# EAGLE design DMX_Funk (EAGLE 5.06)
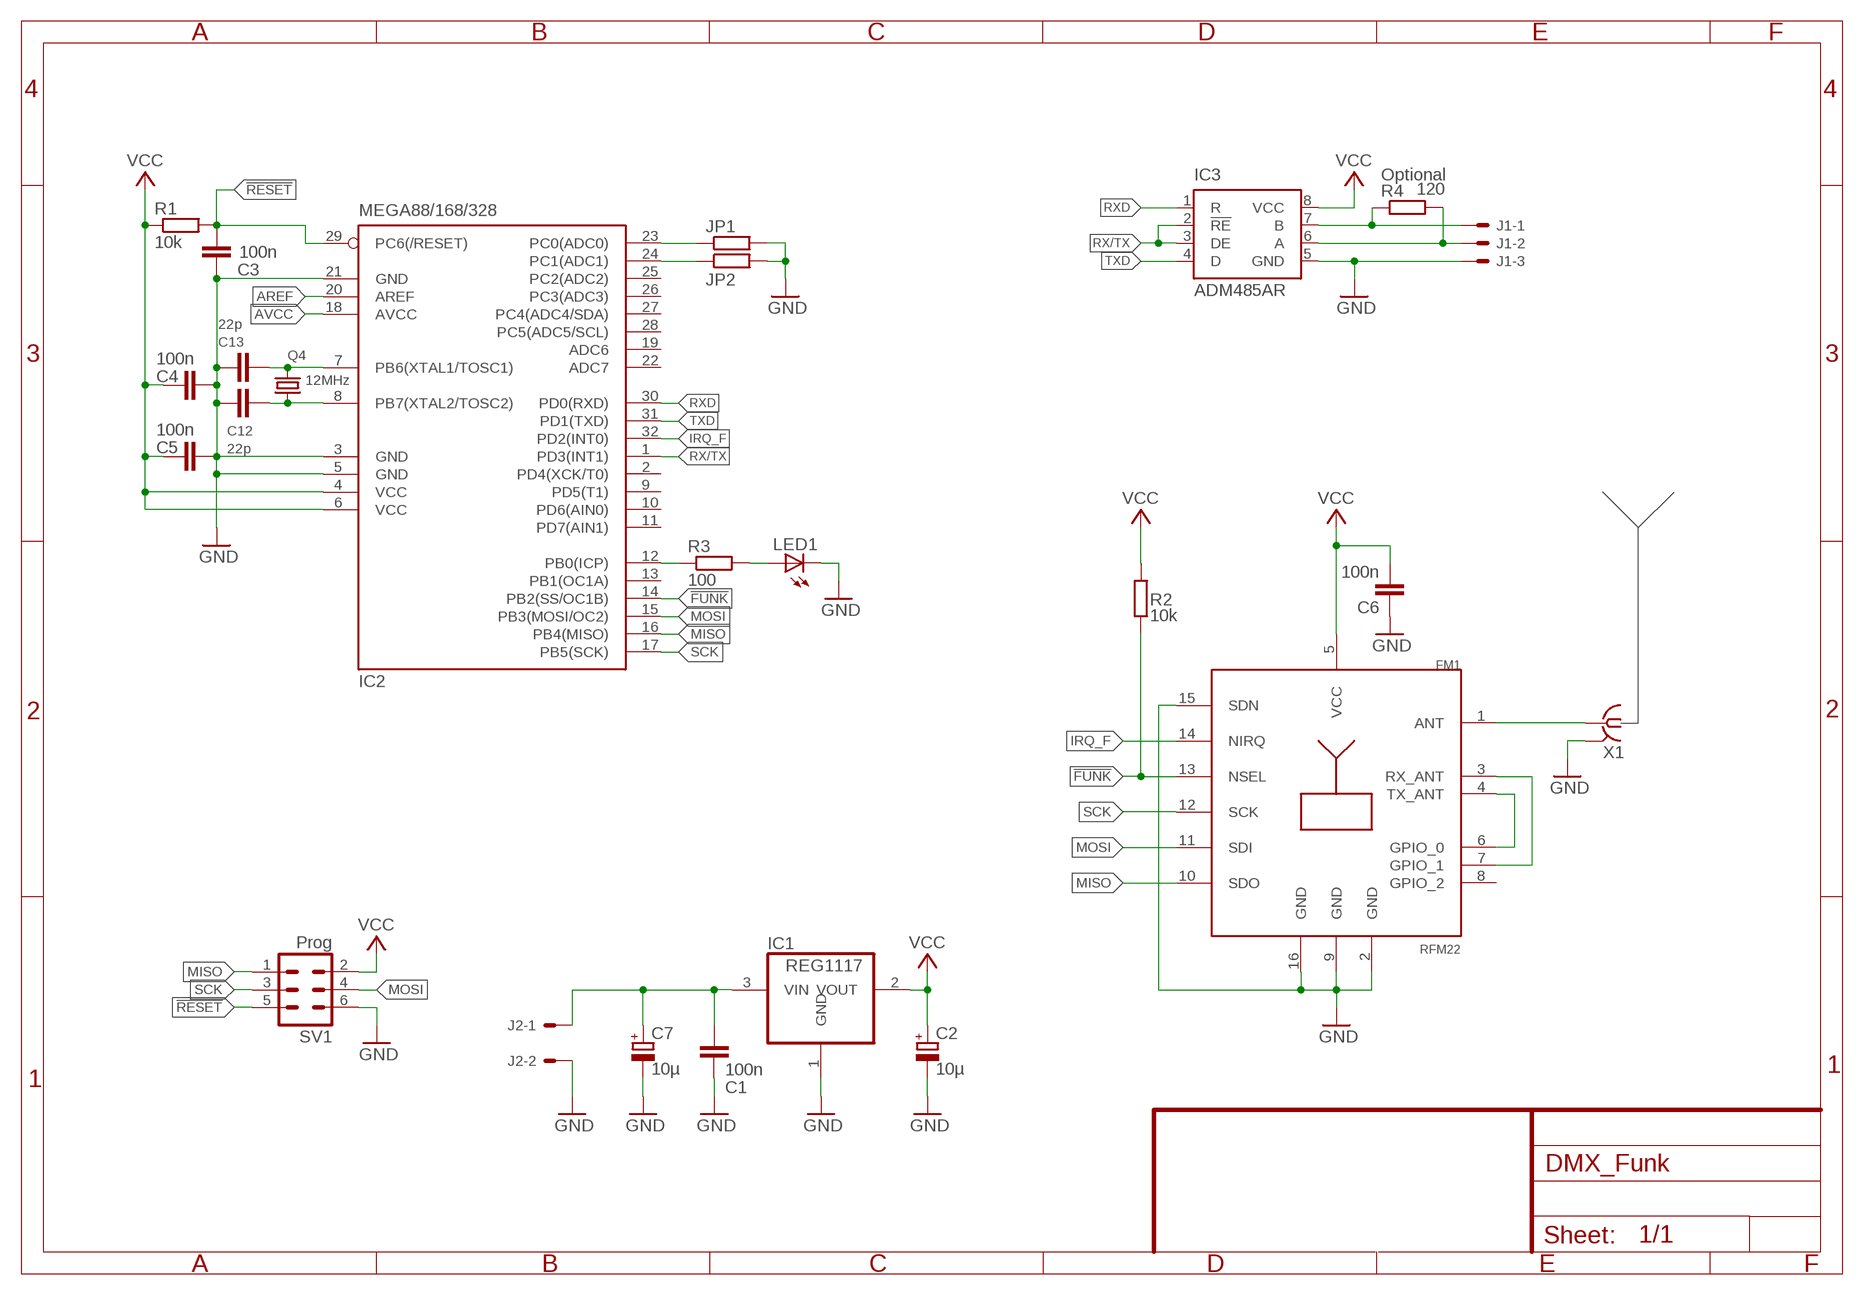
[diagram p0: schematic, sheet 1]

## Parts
C1  100n  C-EUC0805  [C0805]
C2  10µ  CPOL-EUSMCB  [SMC_B]
C3  100n  C-EUC0805  [C0805]
C4  100n  C-EUC0805  [C0805]
C5  100n  C-EUC0805  [C0805]
C6  100n  C-EUC0805  [C0805]
C7  10µ  CPOL-EUSMCB  [SMC_B]
C12  22p  C-EUC0805  [C0805]
C13  22p  C-EUC0805  [C0805]
FM1  RFM22  [RFM22]
IC1  REG1117  [SOT223]
IC2  MEGA88/168/328  MEGA8-AI  [TQFP32-08]
IC3  ADM485AR  SN65176D  [SO-08]
J1  22-27-2031-03  [6410-03]
J2  22-27-2021-02  [6410-02]
JP1  R-EU_R0402  [R0402]
JP2  R-EU_R0402  [R0402]
LED1  LEDSMT1206  [1206]
Q4  12MHz  CRYSTALCTS406  [CTS406]
R1  10k  R-EU_R0805  [R0805]
R2  10k  R-EU_R0805  [R0805]
R3  100  R-EU_R0805  [R0805]
R4  120  R-EU_M0805  [M0805]
SV1  Prog  ML6  [ML6]
X1  BU-SMC-V  [BU-SMC-V]

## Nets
!FUNK: FM1.13(NSEL) IC2.14(PB2(SS/OC1B)) R2.1
!RESET: C3.2 IC2.29(PC6(/RESET)) R1.2 SV1.5
AREF: IC2.20(AREF)
AVCC: IC2.18(AVCC)
GND: C1.1 C2.- C3.1 C4.2 C5.2 C6.1 C7.- C12.1 C13.1 FM1.2(GND) FM1.9(GND) FM1.15(SDN) FM1.16(GND) IC1.1(GND) IC2.3(GND) IC2.5(GND) IC2.21(GND) IC3.5(GND) J1.3 J2.2 JP1.2 JP2.2 LED1.C SV1.6 X1.2(GND)
IRQ_F: FM1.14(NIRQ) IC2.32(PD2(INT0))
MISO: FM1.10(SDO) IC2.16(PB4(MISO)) SV1.1
MOSI: FM1.11(SDI) IC2.15(PB3(MOSI/OC2)) SV1.4
N$1: FM1.4(TX_ANT) FM1.6(GPIO_0)
N$2: IC3.7(B) J1.1 R4.1
N$3: FM1.3(RX_ANT) FM1.7(GPIO_1)
N$4: FM1.1(ANT) X1.1
N$5: IC3.6(A) J1.2 R4.2
N$6: IC2.23(PC0(ADC0)) JP1.1
N$7: IC2.24(PC1(ADC1)) JP2.1
N$8: C1.2 C7.+ IC1.3(VIN) J2.1
N$18: IC2.12(PB0(ICP)) R3.1
N$19: LED1.A R3.2
N$26: C13.2 IC2.7(PB6(XTAL1/TOSC1)) Q4.3
N$27: C12.2 IC2.8(PB7(XTAL2/TOSC2)) Q4.1
RX/TX: IC2.1(PD3(INT1)) IC3.2(!RE) IC3.3(DE)
RXD: IC2.30(PD0(RXD)) IC3.1(R)
SCK: FM1.12(SCK) IC2.17(PB5(SCK)) SV1.3
TXD: IC2.31(PD1(TXD)) IC3.4(D)
VCC: C2.+ C4.1 C5.1 C6.2 FM1.5(VCC) IC1.2(VOUT) IC2.4(VCC) IC2.6(VCC) IC3.8(VCC) R1.1 R2.2 SV1.2
Unconnected: FM1.8(GPIO_2) IC2.2(PD4(XCK/T0)) IC2.9(PD5(T1)) IC2.10(PD6(AIN0)) IC2.11(PD7(AIN1)) IC2.13(PB1(OC1A)) IC2.19(ADC6) IC2.22(ADC7) IC2.25(PC2(ADC2)) IC2.26(PC3(ADC3)) IC2.27(PC4(ADC4/SDA)) IC2.28(PC5(ADC5/SCL))

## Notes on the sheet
- Optional

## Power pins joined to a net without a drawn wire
GND: X1.3(GND) X1.4(GND) X1.5(GND)

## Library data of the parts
C1 C3-C6 C12 C13 = rcl:C-EU: CAPACITOR, European symbol
C2 C7 = rcl:CPOL-EU: POLARIZED CAPACITOR, European symbol
FM1 = RFMxx:RFM22
IC1 = burr-brown:REG1117: 800mA and 1A Low Dropout (LDO) Positive Regulator 1.8V, 2.5V, 2.85V, 3.3V, 5V, and Adj
IC2 = atmel:MEGA8: MICROCONTROLLER 8 Kbytes FLASH, 1 kbytes SRAM, 512 bytes EEPROM, USART, 6-channel 10 bit ADC, 2-channel 8 bit ADC Pin compatible with Atmega48, ATMega88, ATMega168 Source: avr.lbr
IC3 = texas:SN65176: DIFFERENTIAL BUS TRANSCEIVER Source: http://focus.ti.com .. sn65176b.pdf
J1 = con-molex:22-?-03: CONNECTOR wire to board 2.54 mm (.1 inch) pitch header
J2 = con-molex:22-?-02: CONNECTOR
JP1 JP2 R1-R4 = rcl:R-EU_: RESISTOR, European symbol
LED1 = led:LED: LED
Q4 = crystal:CRYSTAL: CRYSTAL
SV1 = con-harting-ml:ML6: HARTING
X1 = con-coax:BU-SMC-V: FEMALE SMC CONNECTOR Radiall R112 426 distributor RS 295-5429

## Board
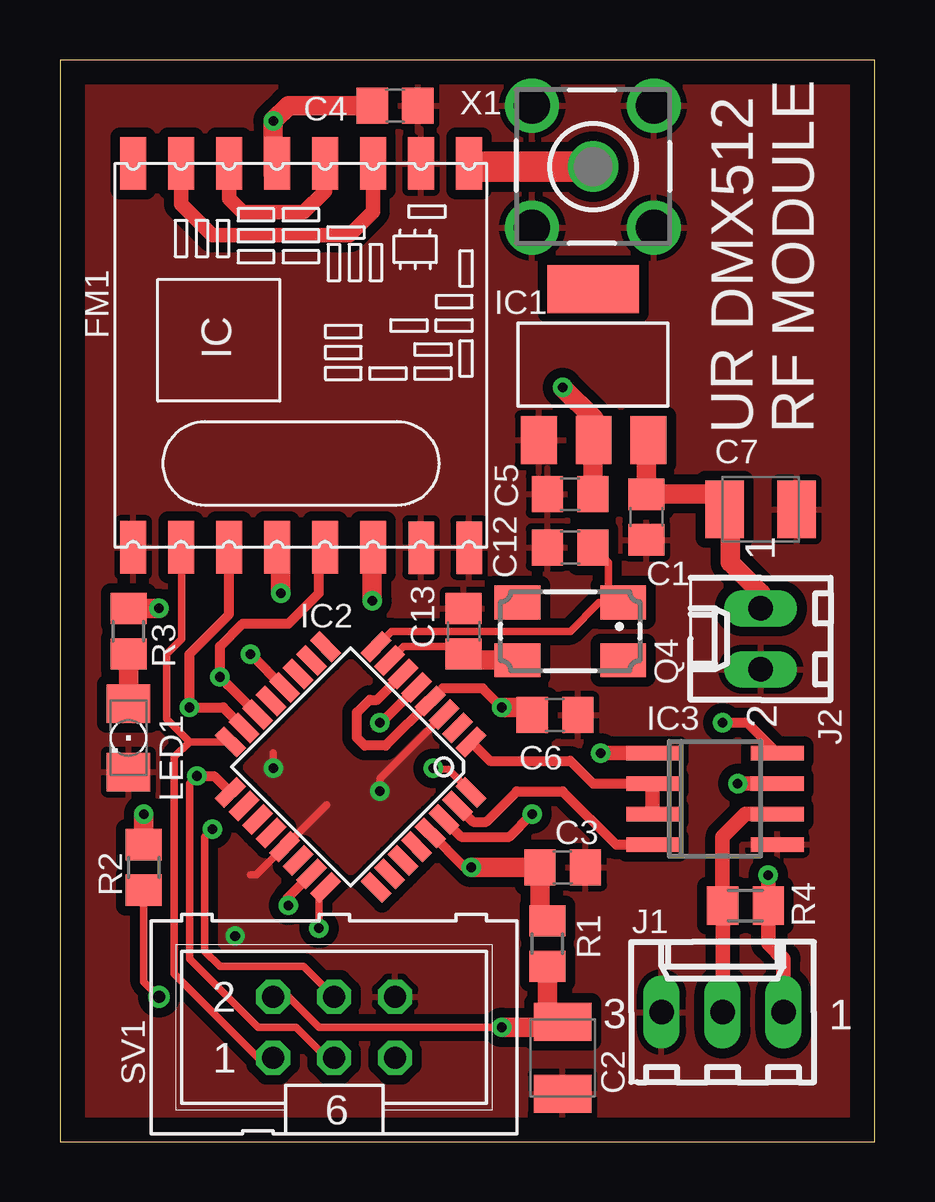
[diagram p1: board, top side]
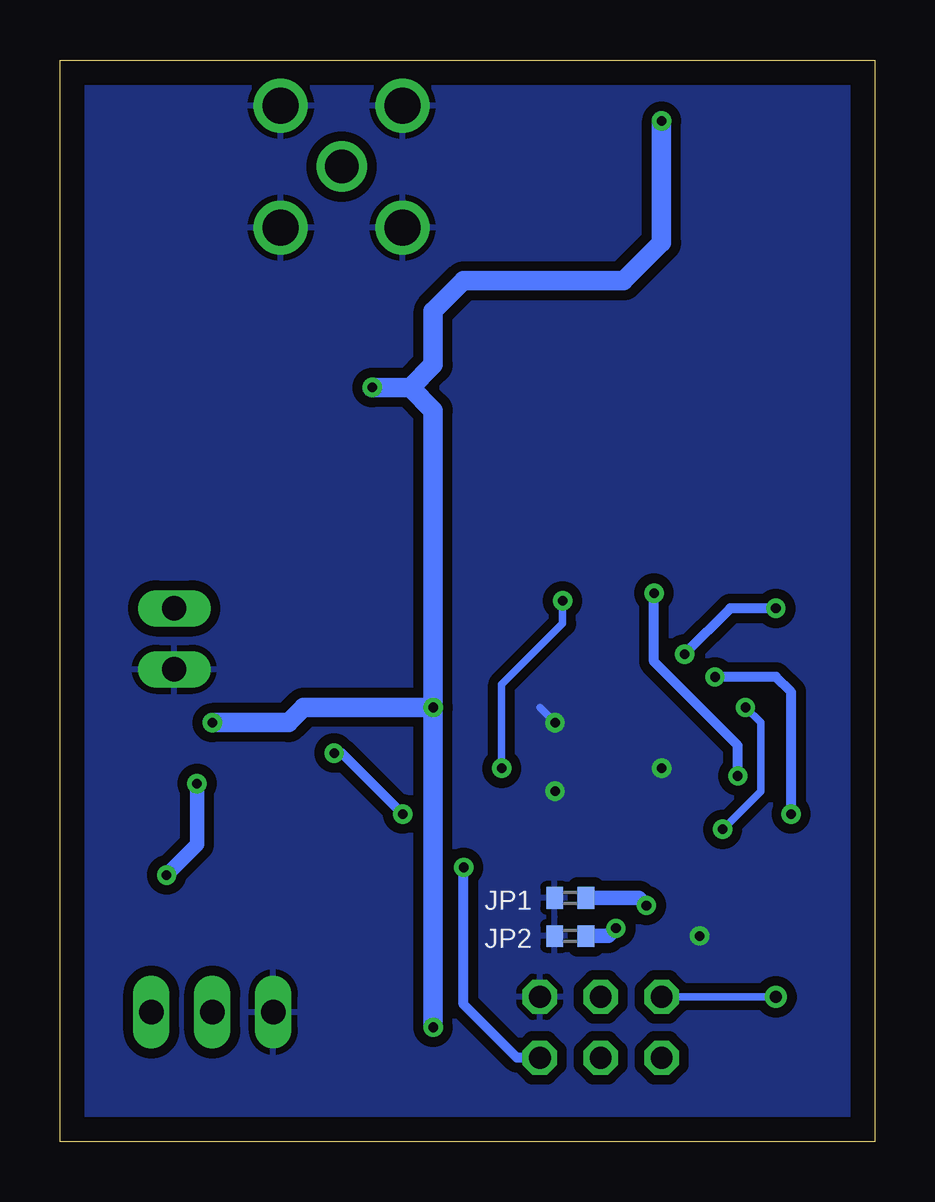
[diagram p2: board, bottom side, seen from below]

Size 33.97 x 45.09 mm. Coordinates in mm from the lower left corner, seen from the top.
Outline: 0,0 33.97,0 33.97,45.09 0,45.09 0,0
Copper layers (1*16): Top 0.035mm / dielectric 1.5mm / Bottom 0.035mm
Design rules "default": minimum track width 10mil, minimum drill 24mil, track to track 8mil, track to pad 8mil, pad to pad 8mil, via to via 8mil, smd to smd 8mil, copper to edge 40mil, drill to drill 8mil, minimum pad ring 10mil, minimum via ring 8mil, stop-mask expansion 4mil, vias tented up to drill 0mil, thermal gap 10mil

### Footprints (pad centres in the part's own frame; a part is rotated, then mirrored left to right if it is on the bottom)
C0805 = smd 1.3 x 1.5: 1 -0.95,0; 2 0.95,0
SMC_B = smd 1.6 x 2.4: + -1.5,0; - 1.5,0
RFM22 = smd 2.184 x 1.067: 1 -8.38,5.62; 2 -8.38,3.62; 3 -8.38,1.62; 4 -8.38,-0.38; 5 -8.38,-2.38; 6 -8.38,-4.38; 7 -8.38,-6.38; 8 -8.38,-8.38; 9 7.62,-8.38; 10 7.62,-6.38; 11 7.62,-4.38; 12 7.62,-2.38; 13 7.62,-0.38; 14 7.62,1.62; 15 7.625,3.625; 16 7.625,5.625
SOT223 = smd 1.499 x 2.007: 1 -2.261,-3.15; 2 0.025,-3.15; 3 2.311,-3.15 | smd 3.81 x 2.007: 4 0,3.15
TQFP32-08 = smd 1.27 x 0.559: 1 -4.293,2.8; 2 -4.293,2; 3 -4.293,1.2; 4 -4.293,0.4; 5 -4.293,-0.4; 6 -4.293,-1.2; 7 -4.293,-2; 8 -4.293,-2.8; 17 4.293,-2.8; 18 4.293,-2; 19 4.293,-1.2; 20 4.293,-0.4; 21 4.293,0.4; 22 4.293,1.2; 23 4.293,2; 24 4.293,2.8 | smd 0.559 x 1.27: 9 -2.8,-4.293; 10 -2,-4.293; 11 -1.2,-4.293; 12 -0.4,-4.293; 13 0.4,-4.293; 14 1.2,-4.293; 15 2,-4.293; 16 2.8,-4.293; 25 2.8,4.293; 26 2,4.293; 27 1.2,4.293; 28 0.4,4.293; 29 -0.4,4.293; 30 -1.2,4.293; 31 -2,4.293; 32 -2.8,4.293
SO-08 = smd 0.6 x 2.2: 1 -1.905,-2.6; 2 -0.635,-2.6; 3 0.635,-2.6; 4 1.905,-2.6; 5 1.905,2.6; 6 0.635,2.6; 7 -0.635,2.6; 8 -1.905,2.6
6410-03 = drill 1.016 long: 1 2.54,0; 2 0,0; 3 -2.54,0
6410-02 = drill 1.016 long: 1 1.27,0; 2 -1.27,0
R0402 = smd 0.7 x 0.9: 1 -0.65,0; 2 0.65,0
1206 = smd 1.6 x 1.803: A -1.422,0; C 1.422,0
CTS406 = smd 1.9 x 1.4: 1 -2.2,-1.2; 2 2.2,-1.2; 3 2.2,1.2; 4 -2.2,1.2
R0805 = smd 1.3 x 1.5: 1 -0.95,0; 2 0.95,0
M0805 = smd 1.3 x 1.6: 1 -0.95,0; 2 0.95,0
ML6 = drill 0.914 octagon: 1 -2.54,-1.27; 2 -2.54,1.27; 3 0,-1.27; 4 0,1.27; 5 2.54,-1.27; 6 2.54,1.27
BU-SMC-V = drill 1.4 round: 1 0,0 | drill 1.5 round: 2 -2.54,2.54; 3 2.54,2.54; 4 2.54,-2.54; 5 -2.54,-2.54

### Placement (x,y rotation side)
C1  24.45,26.04 90 top
C2  20.95,3.49 270 top
C3  20.95,11.43 180 top
C4  13.97,43.18 0 top
C5  21.27,26.99 180 top
C6  20.64,17.78 180 top
C7  29.21,26.35 0 top
C12  21.27,24.77 0 top
C13  16.83,21.27 270 top
FM1  11.43,32.38 270 top
IC1  22.23,32.38 0 top
IC2  12.12,15.61 225 top
IC3  27.3,14.29 270 top
J1  27.62,5.4 0 top
J2  29.21,20.95 90 top
JP1  12.7,10.16 180 bottom
JP2  12.7,8.57 180 bottom
LED1  2.86,16.83 270 top
Q4  21.27,21.27 180 top
R1  20.32,8.26 90 top
R2  3.49,11.43 270 top
R3  2.86,21.27 270 top
R4  28.57,9.84 180 top
SV1  11.43,4.76 0 top
X1  22.23,40.64 90 top

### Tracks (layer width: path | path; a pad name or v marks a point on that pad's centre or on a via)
!FUNK  (via drill 0.4)
  Top 0.305: 10.79,24.51 FM1.13
  Top 0.406: IC2.14 6.98,19.05 v6.67,19.37 6.67,20.64 7.62,21.59 9.53,21.59 10.79,22.86 10.79,24.51
  Top 0.813: R2.1 v3.49,13.65
  Bottom 0.406: v6.67,19.37 4.13,19.37 3.49,18.73 v3.49,13.65
!RESET  (via drill 0.4)
  Top 0.406: 15.4,12.86 IC2.29 16.87,11.43 v17.14,11.43 | C3.2
  Top 0.61: C3.2 20.32,11.12 20,11.11
  Top 0.813: v17.14,11.43 C3.2 | 20,11.11 20,9.21 R1.2
  Bottom 0.406: SV1.5 14.92,3.49 17.14,5.71 v17.14,11.43
GND  (via drill 0.4)
  Top 0.305: v13.34,17.46 13.4,17.46 | IC2.3 13.34,15.13 v13.34,14.61 | v8.89,15.56 8.89,16.19 | 7.94,11.11 8.19,11.11 IC2.21 9.97,12.89 | 9.97,12.89 9.53,12.45 9.53,12.38 | 9.97,12.89 11.11,14.04
  Top 0.406: 13.4,17.46 IC2.5
  Bottom 0.305: v13.34,17.46 13.97,18.1
  other vias: 7.3,8.57
  pour Bottom (isolate 0.406): 0,45.09 33.97,45.09 33.97,0 0,0
  pour Top (isolate 0.406): 0,45.09 33.97,45.09 33.97,0 0,0
IRQ_F  (via drill 0.4)
  Top 0.305: IC2.32 16.19,15.52 v15.56,15.56 | 13.02,24.73 FM1.14
  Top 0.813: v13.02,22.54 13.02,24.73
  Bottom 0.305: v15.56,15.56 15.56,19.05 13.02,21.59 v13.02,22.54
MISO
  Top 0.305: 5.4,16.67 IC2.16 | FM1.10 5.08,24.73 5.08,20.95 4.45,20.32 4.45,17.62 5.4,16.67 | SV1.1 8.26,3.49 4.76,6.99 4.76,16.03 5.4,16.67
MOSI  (via drill 0.4)
  Top 0.305: SV1.4 10.16,7.3 6.67,7.3 6.03,7.94 6.03,12.7 v6.35,13.02
  Top 0.406: IC2.15 6.8,18.1 v5.4,18.1 5.4,20.32 7.05,21.97 FM1.11
  Bottom 0.305: v6.35,13.02 6.03,13.34 4.76,14.61 4.76,17.46 v5.4,18.1
N$1
  Top 0.61: FM1.6 7.05,39.3 7.62,38.73 10.16,38.73 11.05,39.62 FM1.4
N$2  (via drill 0.4)
  Top 0.305: R4.1
  Top 0.61: J1.1 30.16,7.62 29.53,8.26 R4.1 | v28.26,14.92 IC3.7 | R4.1 v29.53,11.11
  Top 0.813: R4.1
  Bottom 0.61: v28.26,14.92 28.26,12.38 v29.53,11.11
N$3
  Top 0.61: FM1.7 5.05,39.08 6.35,37.78 12.06,37.78 13.05,38.77 FM1.3
N$4
  Top 0.406: FM1.1 17.14,39.91 17.14,40.64
  Top 1.27: 17.14,40.64 X1.1
N$5
  Top 0.305: R4.2
  Top 0.61: J1.2 R4.2 | IC3.6 28.57,13.65 27.62,12.7 R4.2
  Top 0.813: J1.2
N$6  (via drill 0.4)
  Top 0.406: v9.53,9.84 9.5,10.16 IC2.23
  Bottom 0.61: v9.53,9.84 9.84,10.16 JP1.1
N$7  (via drill 0.4)
  Top 0.305: IC2.24 10.79,10.33 v10.79,8.89
  Bottom 0.61: JP2.1 11.11,8.57 v10.79,8.89
N$8
  Top 0.406: 24.45,29.23 IC1.3 | C1.2 24.77,26.99 | C7.+ 27.62,25.8
  Top 0.813: C1.2 24.45,29.23 | 24.77,26.99 27.62,26.99 27.62,25.8 | J2.1 29.21,22.86 27.94,24.13 27.94,25.8 C7.+
N$18  (via drill 0.4)
  Top 0.305: R3.1
  Top 0.406: IC2.12 9.33,18.93 v7.94,20.32
  Top 0.813: R3.1 v4.13,22.23
  Bottom 0.406: v7.94,20.32 6.03,22.23 v4.13,22.23
N$19
  Top 0.813: LED1.A R3.2
N$26
  Top 0.305: IC2.7 14.32,20.64 16.19,20.64 16.51,20.32 C13.2 17.08,20.07
  Top 0.813: 17.08,20.07 Q4.3
N$27
  Top 0.305: IC2.8 13.82,21.27 21.27,21.27 22.47,22.47 22.86,22.47 | 22.86,22.47 Q4.1 | C12.2 22.86,24.13 22.86,22.47
RX/TX
  Top 0.406: IC2.1 17.93,15.88 21.27,15.88 22.23,14.92 IC3.2
  Top 0.61: IC3.2 IC3.3
RXD  (via drill 0.4)
  Top 0.406: IC2.30 16.73,12.7 18.73,12.7 v19.68,13.65
  Top 0.61: v22.54,16.19 IC3.1
  Bottom 0.406: v19.68,13.65 22.23,16.19 v22.54,16.19
SCK  (via drill 0.4)
  Top 0.254: 9.21,24.92 FM1.12
  Top 0.305: SV1.3 11.11,3.49 9.84,4.76 8.26,4.76 5.4,7.62 5.4,14.92 v5.71,15.24
  Top 0.406: IC2.17 6.42,15.24 v5.71,15.24
  Top 0.813: v9.21,22.86 9.21,24.92
  Bottom 0.406: v5.71,15.24 5.71,16.51 9.21,20 v9.21,22.86
TXD
  Top 0.406: IC2.31 17.23,13.34 17.78,13.34 19.05,14.61 20.95,14.61 23.18,12.38 IC3.4
VCC  (via drill 0.4, 0.5)
  Top 0.305: SV1.2 9.53,6.03 10.79,4.76 v18.41,4.76 | 19.69,18.1 C6.2 | 20.32,4.76 20.55,4.99 C2.+ | v4.13,6.03 3.49,6.67 R2.2 | IC1.2 22.22,29.21
  Top 0.406: v18.41,18.1 17.62,18.89 15.96,18.89 IC2.4 13.58,16.51 12.7,16.51 12.38,16.83 12.38,17.89 12.91,18.41 13.23,18.41 IC2.6 | IC3.8 28.64,17.46 v27.62,17.46
  Top 0.61: 9.05,40.16 FM1.5 | 22.25,30.14 IC1.2
  Top 0.813: 9.05,40.16 8.89,40.32 v8.89,42.55 9.53,43.18 C4.1 | v18.41,18.1 19.69,18.1 | v18.41,4.76 20.32,4.76 R1.1 | 22.22,29.21 C5.1 | v20.95,31.43 22.25,30.14
  Bottom 0.305: 3.81,6.03 v4.13,6.03 SV1.2
  Bottom 0.813: v18.41,4.76 v18.41,18.1 | v8.89,42.55 8.89,37.47 10.48,35.88 17.14,35.88 18.41,34.61 18.41,32.38 19.37,31.43 | 19.37,31.43 v20.95,31.43 | v18.41,18.1 18.41,30.48 19.37,31.43 | v18.41,18.1 23.81,18.1 24.45,17.46 v27.62,17.46

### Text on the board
tPlace: UR DMX512 | RF MODULE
